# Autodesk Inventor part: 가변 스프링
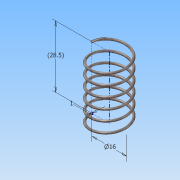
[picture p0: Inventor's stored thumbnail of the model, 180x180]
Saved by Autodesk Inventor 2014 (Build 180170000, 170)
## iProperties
Created: 2016-05
Part Number: 가변 스프링
Material: 스테인레스 스틸
Document SubType Name: Modeling
Designer: 703-04
Mass: 1.90231 g
Surface Area: 9.49542 cm^2
Volume: 0.235434 cm^3
Density: 8.08 g/cm^3
Appearance: 반연마
Author: 703-04
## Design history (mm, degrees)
sketch "스케치2"
  geometry: L1 (0, 0)-(8, 0); L2 (8, 0)-(8, 28.5); L3 (8, 28.5)-(0, 28.5); L4 (0, 28.5)-(0, 0); C1 r 0.5 at (8, 0)
  constraints: 8 end point, 2 parallel, 1 centre point, 1 coincident, 1 horizontal, 1 perpendicular
  dimensions: "d0" = 16 diameter of L2 L4; "d1" = 28.49959 distance between parallel lines of L3 L1 (derived); "d2" = 1 diameter of C1
feature "코일1" pitch "d3" = 10; turns "d5" = 6; dims "d4" = 28.49959 (= d1), "d6" = 0, angle "d7" = 90 deg, angle "d8" = 90 deg, "d9" = 0, "d10" = 0
sketch "스케치3"
  geometry: L1 (-8.5, 0)-(-7.5, 0) reference; 1 further point
  constraints: 1 horizontal alignment
extrude "돌출1" cut sketch "스케치3" stored distance "d11" = 10; taper "d12" = 0 deg
node "작업 평면1"
sketch "스케치4"
  geometry: L1 (8.5, 0)-(7.5, 0) reference; 1 further point
  constraints: 1 horizontal alignment
extrude "돌출2" cut sketch "스케치4" stored distance "d13" = 10; taper "d14" = 0 deg
node "솔리드1"
node "절단 모서리 투영1"
node "절단 모서리 투영2"
